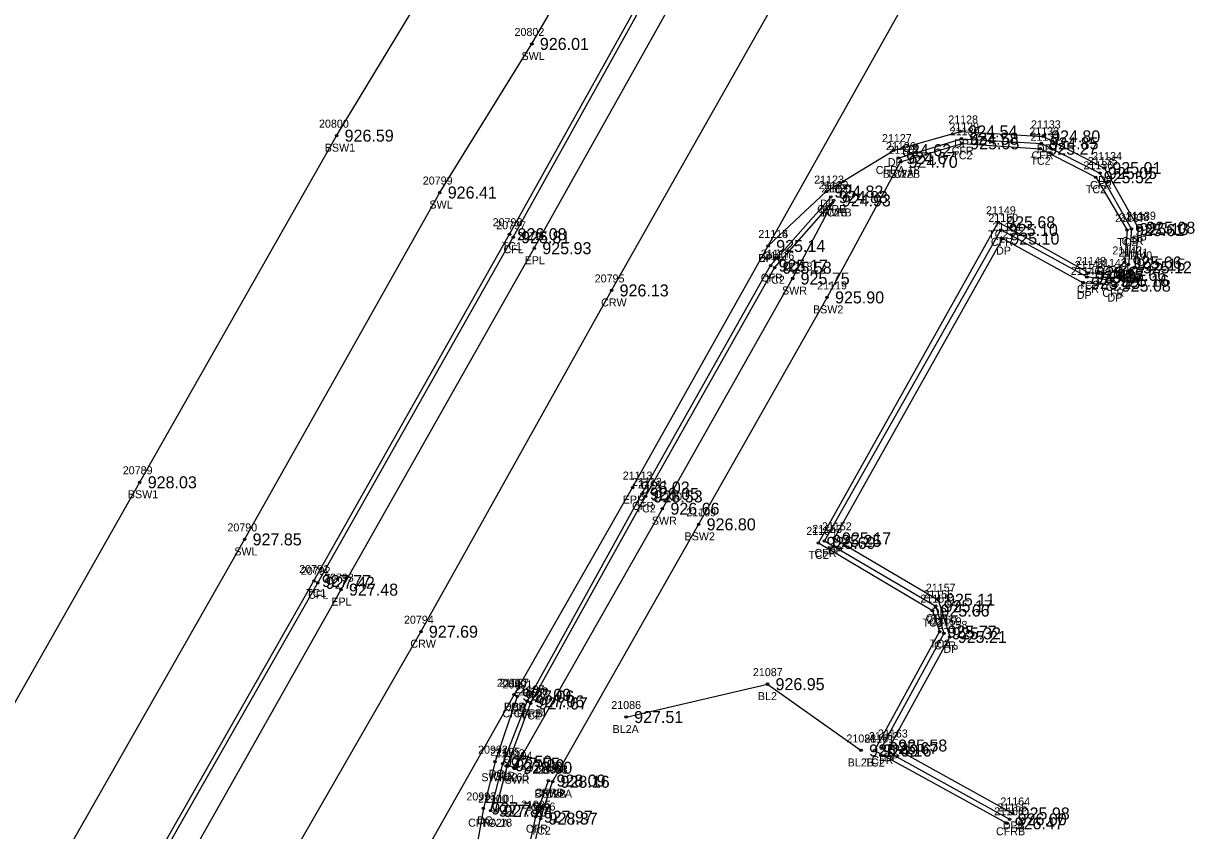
# Model space of a CAD drawing. Extents: x 1576181 to 1577685, y 1099396 to 1101490.
# Drawn here: x 1576724.5 to 1576872.4, y 1100179 to 1100279.9 of the extents above; entities that cross this region are included whole.
import ezdxf

# ---------------------------------------------------------------- set-up
doc = ezdxf.new("R2010")
doc.units = 0
for name, color, linetype in [('RD_DTM_BkLn1', 7, 'Continuous'), ('RD_DTM_BkLn2', 7, 'Continuous'), ('RD_DTM_BkLn_txCode', 7, 'Continuous'), ('RD_EX_Conc', 7, 'Continuous'), ('RD_EX_Conc_txCode', 7, 'Continuous'), ('RD_EX_Driveway', 7, 'Continuous'), ('RD_EX_Driveway_txCode', 7, 'Continuous'), ('RD_EX_Road', 7, 'Continuous'), ('RD_EX_Road_txCode', 7, 'Continuous'), ('RD_EX_TX_Conc_ELEV', 7, 'Continuous'), ('RD_EX_TX_Driveway_ELEV', 7, 'Continuous'), ('RD_EX_TX_Misc_ELEV', 7, 'Continuous'), ('RD_EX_TX_Road_ELEV', 7, 'Continuous'), ('RD_HC_Survey_ELEV', 7, 'Continuous'), ('RD_HC_Survey_txCode', 7, 'Continuous'), ('RD_SMD_Locator', 7, 'Continuous')]:
    doc.layers.add(name, color=color, linetype=linetype)

msp = doc.modelspace()

# ---------------------------------------------------------------- linework, layer by layer
at = {"layer": 'RD_DTM_BkLn1'}
for points in [[(1576435.96, 1099635.47), (1576469.98, 1099685.91), (1576496.51, 1099728.46), (1576522.67, 1099770.85), (1576549.06, 1099813.4), (1576563.36, 1099837.2), (1576575.09, 1099855.95), (1576600.75, 1099898.96), (1576625.57, 1099942.14), (1576652.37, 1099988.91), (1576675.03, 1100029.12), (1576699.51, 1100072.44), (1576723.52, 1100115.7), (1576748.08, 1100158.53), (1576774.13, 1100203.85), (1576797.97, 1100246.52), (1576822.46, 1100289.82), (1576846.93, 1100333.35), (1576871.37, 1100376.46), (1576888.27, 1100406.22)], [(1576799.79, 1100193.18), (1576817.46, 1100197.29), (1576829.16, 1100189)]]:
    msp.add_lwpolyline(points, dxfattribs=at)
at = {"layer": 'RD_DTM_BkLn2'}
for points in [[(1576569.71, 1099889.13), (1576574.56, 1099891.34), (1576579.27, 1099894.47), (1576584.19, 1099899.55), (1576592.25, 1099913.59), (1576612.84, 1099949.87), (1576637.54, 1099993.05), (1576637.54, 1099993.05), (1576662.19, 1100036.34), (1576686.67, 1100079.69), (1576711.46, 1100123.12), (1576735.92, 1100166.59), (1576760.76, 1100210.19), (1576785.21, 1100253.55), (1576809.13, 1100296.43), (1576833.85, 1100340.61), (1576852.06, 1100373.52), (1576858.66, 1100385.37)], [(1576834.09, 1100262.6), (1576841.79, 1100264.91), (1576851.56, 1100264.23), (1576858.48, 1100260.67), (1576862.4, 1100254.06), (1576862.08, 1100250.02), (1576860.15, 1100248.47), (1576857.56, 1100248.71), (1576846.29, 1100255.04), (1576823.82, 1100214.95), (1576838.08, 1100206.49), (1576838.96, 1100203.86), (1576830.82, 1100188.99), (1576847.35, 1100179.89)], [(1576783.46, 1100181.45), (1576784.94, 1100187.15), (1576787.85, 1100194.88), (1576802.21, 1100220.76), (1576818.34, 1100249.36), (1576825.74, 1100257.77)], [(1576787.7, 1100170.21), (1576787.99, 1100175.73), (1576789.09, 1100180.48), (1576790.59, 1100185.09)]]:
    msp.add_lwpolyline(points, dxfattribs=at)
at = {"layer": 'RD_EX_Conc'}
for points in [[(1576537.53, 1099904.47), (1576543.86, 1099909.52), (1576562.16, 1099910.99), (1576591.51, 1099962.44), (1576615.66, 1100005.02), (1576615.66, 1100005.02), (1576639.95, 1100047.65), (1576665.61, 1100092.87), (1576689.57, 1100135.17), (1576714.68, 1100179.66), (1576738.99, 1100222.53), (1576763.6, 1100265.87), (1576774.84, 1100284.48), (1576788.69, 1100308.17), (1576806.14, 1100353.34), (1576815.02, 1100384.28), (1576820.35, 1100399.92), (1576825.22, 1100406.93), (1576832.15, 1100418.17), (1576835.04, 1100423.11), (1576847.13, 1100416.35), (1576868.44, 1100408.23), (1576872.09, 1100412.69)], [(1576592.25, 1099913.59), (1576580.2, 1099912.49), (1576604.17, 1099954.86), (1576628.85, 1099997.89), (1576628.85, 1099997.89), (1576652.81, 1100040.47), (1576678.28, 1100085.17), (1576702.19, 1100127.32), (1576727.43, 1100172.04), (1576752.1, 1100215.39), (1576776.49, 1100258.76), (1576788, 1100277.34), (1576801.96, 1100301.42), (1576820.18, 1100348.3), (1576829.19, 1100379.59), (1576833.87, 1100393.41), (1576838.32, 1100402.43), (1576861.82, 1100391.11)], [(1576569.87, 1099888.69), (1576574.84, 1099890.86), (1576574.84, 1099890.86), (1576579.65, 1099894.15), (1576584.72, 1099899.29), (1576592.68, 1099913.3), (1576613.45, 1099949.72), (1576638.02, 1099992.78), (1576638.02, 1099992.78), (1576662.6, 1100036.05), (1576687.14, 1100079.44), (1576711.91, 1100122.93), (1576736.42, 1100166.35), (1576761.24, 1100209.96), (1576785.67, 1100253.17), (1576809.57, 1100296.25), (1576834.31, 1100340.56), (1576852.46, 1100373.22), (1576852.46, 1100373.22), (1576859.24, 1100385.1)], [(1576833.8, 1100263.07), (1576841.69, 1100265.49), (1576851.69, 1100264.91), (1576859, 1100261.2), (1576862.95, 1100254.19), (1576862.57, 1100249.76), (1576860.52, 1100247.72), (1576857.37, 1100248.21), (1576846.61, 1100254.09), (1576824.56, 1100215.2), (1576838.48, 1100207.04), (1576839.5, 1100203.64), (1576831.67, 1100189.29), (1576847.72, 1100180.39)], [(1576790.59, 1100185.09), (1576808.85, 1100217.27), (1576824.9, 1100245.65), (1576834.09, 1100262.6)], [(1576782.86, 1100181.47), (1576784.37, 1100187.33), (1576787.42, 1100195.14), (1576787.42, 1100195.14), (1576801.76, 1100221.08), (1576817.85, 1100249.62), (1576825.37, 1100258.19)], [(1576784.94, 1100187.15), (1576785.91, 1100186.84), (1576804.32, 1100219.23), (1576820.59, 1100248.01), (1576825.74, 1100257.77)], [(1576785.78, 1100195.96), (1576786.17, 1100195.75), (1576783.4, 1100187.6), (1576781.94, 1100181.75), (1576781.06, 1100176.61), (1576780.68, 1100170.53), (1576780.65, 1100154.57), (1576781.71, 1100148.92), (1576783.02, 1100145.98), (1576783.87, 1100143), (1576785.93, 1100140.68), (1576788.65, 1100139.28), (1576796.67, 1100133.29), (1576804.55, 1100128.57), (1576819.43, 1100122.6)], [(1576787.28, 1100170.17), (1576787.42, 1100175.79), (1576788.49, 1100180.72), (1576790.08, 1100185.23)]]:
    msp.add_lwpolyline(points, dxfattribs=at)
at = {"layer": 'RD_EX_Driveway'}
msp.add_lwpolyline([(1576817.54, 1100252.08), (1576824.8, 1100258.88), (1576833.27, 1100264.06), (1576841.56, 1100266.4), (1576851.91, 1100265.78), (1576859.56, 1100261.82), (1576863.79, 1100254.36), (1576863.37, 1100249.4), (1576860.73, 1100247.12), (1576856.89, 1100247.45), (1576846.81, 1100253), (1576825.77, 1100215.52), (1576838.77, 1100207.85), (1576840.24, 1100203.2), (1576832.79, 1100189.62), (1576848.1, 1100181.12)], dxfattribs=at)
at = {"layer": 'RD_EX_Road'}
for points in [[(1576574.84, 1099890.86), (1576581.17, 1099887.16), (1576595.39, 1099911.97), (1576615.87, 1099948.17), (1576640.56, 1099991.4), (1576640.56, 1099991.4), (1576664.88, 1100034.19), (1576689.84, 1100078.06), (1576714.22, 1100121.19), (1576739.08, 1100164.66), (1576764.15, 1100209.11), (1576788.31, 1100251.8), (1576812.15, 1100294.46), (1576837.06, 1100339.37), (1576855.38, 1100371.53), (1576853.98, 1100372.48), (1576862.98, 1100388.86), (1576865.16, 1100391.95), (1576873.15, 1100402.8), (1576877.45, 1100410.32)], [(1576663.31, 1099979.53), (1576687.43, 1100021.53), (1576712.03, 1100065.1), (1576738.42, 1100112.14), (1576760.61, 1100151.41), (1576785.78, 1100195.96), (1576800.59, 1100221.87), (1576817.54, 1100252.08), (1576858.25, 1100324.63), (1576880.45, 1100364.01), (1576883.5, 1100369.45), (1576896.98, 1100397.71)]]:
    msp.add_lwpolyline(points, dxfattribs=at)
at = {"layer": 'RD_SMD_Locator'}
for centre in [(1576788, 1100277.34), (1576763.6, 1100265.87), (1576841.56, 1100266.4), (1576841.69, 1100265.49), (1576851.91, 1100265.78), (1576833.27, 1100264.06), (1576841.79, 1100264.91), (1576851.56, 1100264.23), (1576851.69, 1100264.91), (1576833.8, 1100263.07), (1576834.09, 1100262.6), (1576834.09, 1100262.6), (1576858.48, 1100260.67), (1576859, 1100261.2), (1576859.56, 1100261.82), (1576776.49, 1100258.76), (1576824.8, 1100258.88), (1576825.37, 1100258.19), (1576825.74, 1100257.77), (1576825.74, 1100257.77), (1576846.29, 1100255.04), (1576785.21, 1100253.55), (1576785.67, 1100253.17), (1576846.61, 1100254.09), (1576862.4, 1100254.06), (1576862.95, 1100254.19), (1576863.79, 1100254.36), (1576788.31, 1100251.8), (1576817.54, 1100252.08), (1576817.54, 1100252.08), (1576846.81, 1100253), (1576817.85, 1100249.62), (1576818.34, 1100249.36), (1576857.56, 1100248.71), (1576862.08, 1100250.02), (1576862.57, 1100249.76), (1576863.37, 1100249.4), (1576820.59, 1100248.01), (1576856.89, 1100247.45), (1576857.37, 1100248.21), (1576860.15, 1100248.47), (1576860.52, 1100247.72), (1576797.97, 1100246.52), (1576860.73, 1100247.12), (1576824.9, 1100245.65), (1576738.99, 1100222.53), (1576800.59, 1100221.87), (1576801.76, 1100221.08), (1576802.21, 1100220.76), (1576804.32, 1100219.23), (1576808.85, 1100217.27), (1576752.1, 1100215.39), (1576823.82, 1100214.95), (1576824.56, 1100215.2), (1576825.77, 1100215.52), (1576760.76, 1100210.19), (1576761.24, 1100209.96), (1576764.15, 1100209.11), (1576838.77, 1100207.85), (1576838.08, 1100206.49), (1576838.48, 1100207.04), (1576774.13, 1100203.85), (1576838.96, 1100203.86), (1576839.5, 1100203.64), (1576840.24, 1100203.2), (1576817.46, 1100197.29), (1576785.78, 1100195.96), (1576785.78, 1100195.96), (1576786.17, 1100195.75), (1576787.42, 1100195.14), (1576787.42, 1100195.14), (1576787.85, 1100194.88), (1576799.79, 1100193.18), (1576832.79, 1100189.62), (1576829.16, 1100189), (1576830.82, 1100188.99), (1576831.67, 1100189.29), (1576783.4, 1100187.6), (1576784.37, 1100187.33), (1576784.94, 1100187.15), (1576784.94, 1100187.15), (1576785.91, 1100186.84), (1576790.08, 1100185.23), (1576790.59, 1100185.09), (1576790.59, 1100185.09), (1576781.94, 1100181.75), (1576782.86, 1100181.47), (1576783.46, 1100181.45), (1576788.49, 1100180.72), (1576848.1, 1100181.12), (1576789.09, 1100180.48), (1576847.35, 1100179.89), (1576847.72, 1100180.39)]:
    msp.add_circle(centre, 0.15, dxfattribs=at)

# ---------------------------------------------------------------- texts
at = {"layer": 'RD_DTM_BkLn_txCode'}
for s, p in [('21087', (1576815.63, 1100198.29)), ('BL2', (1576816.26, 1100195.29)), ('21086', (1576797.93, 1100194.18)), ('BL2A', (1576798.09, 1100191.18)), ('21088', (1576827.32, 1100190)), ('BL2B', (1576827.48, 1100187))]:
    msp.add_text(s, height=1, dxfattribs=at).set_placement(p)
at = {"layer": 'RD_EX_Conc_txCode'}
for s, p in [('20802', (1576785.84, 1100278.34)), ('SWL', (1576786.71, 1100275.34)), ('20800', (1576761.4, 1100266.87)), ('21129', (1576840.18, 1100266.49)), ('21130', (1576840.24, 1100265.91)), ('21132', (1576850.18, 1100265.91)), ('21131', (1576850.33, 1100265.23)), ('BSW1', (1576762.12, 1100263.87)), ('21126', (1576832.26, 1100264.07)), ('21124', (1576832.57, 1100263.6)), ('21125', (1576832.57, 1100263.6)), ('CFR', (1576840.47, 1100263.49)), ('TC2', (1576840.55, 1100262.91)), ('CFR', (1576850.46, 1100262.91)), ('TC2', (1576850.32, 1100262.23)), ('21136', (1576856.95, 1100261.67)), ('21135', (1576857.49, 1100262.2)), ('20799', (1576774.37, 1100259.76)), ('CFRA 18', (1576830.98, 1100261.07)), ('BSW2B', (1576831.85, 1100260.6)), ('TC2A', (1576832.35, 1100260.6)), ('21122', (1576823.86, 1100259.19)), ('21120', (1576824.19, 1100258.77)), ('21121', (1576824.51, 1100258.77)), ('TC2', (1576857.24, 1100258.67)), ('CFR', (1576857.77, 1100259.2)), ('SWL', (1576775.2, 1100256.76)), ('CFRB', (1576823.67, 1100256.19)), ('SWRB', (1576823.96, 1100255.77)), ('TC2B', (1576824.03, 1100255.77)), ('21149', (1576844.77, 1100256.04)), ('20798', (1576783.1, 1100254.55)), ('20797', (1576783.55, 1100254.17)), ('21150', (1576845.06, 1100255.09)), ('21137', (1576860.89, 1100255.06)), ('21138', (1576861.44, 1100255.19)), ('TC2', (1576845.04, 1100253.04)), ('TC1', (1576784.25, 1100251.55)), ('CFL', (1576784.46, 1100251.17)), ('CFR', (1576845.38, 1100252.09)), ('21142', (1576860.56, 1100251.02)), ('TC2', (1576861.16, 1100252.06)), ('CFR', (1576861.72, 1100252.19)), ('21117', (1576816.62, 1100250.62)), ('21116', (1576817.08, 1100250.36)), ('21148', (1576856.05, 1100249.71)), ('21143', (1576858.64, 1100249.47)), ('21141', (1576861.34, 1100250.76)), ('21118', (1576819.36, 1100249.01)), ('21147', (1576855.86, 1100249.21)), ('21144', (1576859.01, 1100248.72)), ('TC2', (1576860.83, 1100248.02)), ('CFR', (1576816.62, 1100247.62)), ('TC2', (1576817.09, 1100247.36)), ('21119', (1576823.67, 1100246.65)), ('TC2', (1576856.32, 1100246.71)), ('TC2', (1576858.9, 1100246.47)), ('CFR', (1576861.34, 1100247.76)), ('SWR', (1576819.27, 1100246.01)), ('CFR', (1576856.14, 1100246.21)), ('CFR', (1576859.3, 1100245.72)), ('BSW2', (1576823.14, 1100243.65)), ('20789', (1576736.87, 1100223.53)), ('21112', (1576800.53, 1100222.08)), ('21111', (1576801.26, 1100221.76)), ('BSW1', (1576737.51, 1100220.53)), ('21110', (1576803.05, 1100220.23)), ('CFR', (1576800.53, 1100219.08)), ('TC2', (1576800.96, 1100218.76)), ('21109', (1576807.3, 1100218.27)), ('SWR', (1576803, 1100217.23)), ('20790', (1576749.95, 1100216.39)), ('BSW2', (1576807.09, 1100215.27)), ('21154', (1576822.31, 1100215.95)), ('21153', (1576823.05, 1100216.2)), ('SWL', (1576750.81, 1100213.39)), ('TC2', (1576822.58, 1100212.95)), ('CFR', (1576823.33, 1100213.2)), ('20791', (1576758.92, 1100211.19)), ('20792', (1576759.12, 1100210.96)), ('TC1', (1576759.79, 1100208.19)), ('CFL', (1576760.04, 1100207.96)), ('21156', (1576836.95, 1100208.04)), ('21155', (1576836.57, 1100207.49)), ('CFR', (1576837.25, 1100205.04)), ('TC2', (1576836.83, 1100204.49)), ('21160', (1576837.39, 1100204.86)), ('21159', (1576837.99, 1100204.64)), ('TC2', (1576837.72, 1100201.86)), ('CFR', (1576838.27, 1100201.64)), ('20990', (1576783.62, 1100196.96)), ('20991', (1576784.34, 1100196.75)), ('21106', (1576785.85, 1100196.14)), ('21107', (1576785.87, 1100196.14)), ('21108', (1576786.3, 1100195.88)), ('CFRA 24', (1576784.32, 1100193.14)), ('DCA', (1576784.51, 1100193.96)), ('DC', (1576785.39, 1100193.75)), ('CFRB', (1576785.72, 1100193.14)), ('TC2', (1576786.61, 1100192.88)), ('21162', (1576830.13, 1100190.29)), ('21161', (1576829.57, 1100189.99)), ('20992', (1576781.28, 1100188.6)), ('21105', (1576782.82, 1100188.33)), ('21102', (1576783.39, 1100188.15)), ('21103', (1576783.39, 1100188.15)), ('21104', (1576784.36, 1100187.84)), ('CFR', (1576830.44, 1100187.29)), ('21099', (1576788.24, 1100186.23)), ('21097', (1576788.76, 1100186.09)), ('21098', (1576788.76, 1100186.09)), ('TC2', (1576829.58, 1100186.99)), ('SWRA 60', (1576781.69, 1100185.15)), ('DC', (1576782.62, 1100185.6)), ('CFR', (1576783.15, 1100185.33)), ('TC2', (1576783.69, 1100185.15)), ('SWR', (1576784.6, 1100184.84)), ('20993', (1576779.82, 1100182.75)), ('CFRB', (1576788.37, 1100183.23)), ('BSW2A', (1576788.34, 1100183.09)), ('TC2B', (1576788.88, 1100183.09)), ('21100', (1576781.27, 1100182.47)), ('21101', (1576782.19, 1100182.45)), ('21095', (1576786.65, 1100181.72)), ('21096', (1576787.23, 1100181.48)), ('21165', (1576846.19, 1100181.39)), ('21166', (1576845.79, 1100180.89)), ('CFRA 18', (1576780.04, 1100179.47)), ('DC', (1576781.16, 1100179.75)), ('TC2A', (1576781.73, 1100179.45)), ('CFR', (1576787.26, 1100178.72)), ('TC2', (1576787.84, 1100178.48)), ('CFRB', (1576846.02, 1100178.39))]:
    msp.add_text(s, height=1, dxfattribs=at).set_placement(p)
at = {"layer": 'RD_EX_Driveway_txCode'}
for s, p in [('21128', (1576840.05, 1100267.4)), ('21133', (1576850.39, 1100266.78)), ('21127', (1576831.76, 1100265.06)), ('DP', (1576840.78, 1100264.4)), ('DP', (1576851.13, 1100263.78)), ('21134', (1576858.04, 1100262.82)), ('DP', (1576832.49, 1100262.06)), ('21123', (1576823.29, 1100259.88)), ('DP', (1576858.78, 1100259.82)), ('DP', (1576824.02, 1100256.88)), ('21139', (1576862.28, 1100255.36)), ('21151', (1576845.58, 1100254)), ('21115', (1576816.31, 1100253.08)), ('DP', (1576863.01, 1100252.36)), ('DP', (1576846.03, 1100251)), ('DPA', (1576816.28, 1100250.08)), ('21140', (1576861.82, 1100250.4)), ('21146', (1576855.36, 1100248.45)), ('21145', (1576859.21, 1100248.12)), ('DP', (1576862.59, 1100247.4)), ('DP', (1576856.11, 1100245.45)), ('DP', (1576859.95, 1100245.12)), ('21152', (1576824.26, 1100216.52)), ('DP', (1576824.99, 1100213.52)), ('21157', (1576837.25, 1100208.85)), ('DP', (1576837.99, 1100205.85)), ('21158', (1576838.72, 1100204.2)), ('DP', (1576839.46, 1100201.2)), ('21163', (1576831.26, 1100190.62)), ('DP', (1576832.01, 1100187.62)), ('21164', (1576846.56, 1100182.12)), ('DPB', (1576846.85, 1100179.12))]:
    msp.add_text(s, height=1, dxfattribs=at).set_placement(p)
at = {"layer": 'RD_EX_Road_txCode'}
for s, p in [('20796', (1576786.17, 1100252.8)), ('21114', (1576816.31, 1100253.08)), ('EPL', (1576787.1, 1100249.8)), ('EPR', (1576816.31, 1100250.08)), ('21113', (1576799.36, 1100222.87)), ('EPR', (1576799.36, 1100219.87)), ('20793', (1576762.03, 1100210.11)), ('EPL', (1576762.94, 1100207.11)), ('21067', (1576783.92, 1100196.96)), ('EPR', (1576784.55, 1100193.96))]:
    msp.add_text(s, height=1, dxfattribs=at).set_placement(p)
at = {"layer": 'RD_EX_TX_Conc_ELEV'}
for s, p in [('926.01', (1576789, 1100276.59)), ('926.59', (1576764.6, 1100265.12)), ('924.58', (1576842.69, 1100264.74)), ('925.05', (1576842.79, 1100264.16)), ('924.85', (1576852.69, 1100264.16)), ('924.67', (1576834.8, 1100262.32)), ('925.27', (1576852.56, 1100263.48)), ('924.70', (1576835.09, 1100261.85)), ('924.70', (1576835.09, 1100261.85)), ('925.52', (1576859.48, 1100259.92)), ('925.05', (1576860, 1100260.45)), ('926.41', (1576777.49, 1100258.01)), ('924.83', (1576826.37, 1100257.44)), ('924.93', (1576826.74, 1100257.02)), ('924.93', (1576826.74, 1100257.02)), ('925.68', (1576847.29, 1100254.29)), ('925.10', (1576847.61, 1100253.34)), ('925.61', (1576863.4, 1100253.31)), ('925.13', (1576863.95, 1100253.44)), ('926.08', (1576786.21, 1100252.8)), ('925.81', (1576786.67, 1100252.42)), ('925.17', (1576818.85, 1100248.87)), ('925.66', (1576863.08, 1100249.27)), ('925.15', (1576863.57, 1100249.01)), ('925.58', (1576819.34, 1100248.61)), ('925.17', (1576858.37, 1100247.46)), ('925.67', (1576858.56, 1100247.96)), ('925.66', (1576861.15, 1100247.72)), ('925.75', (1576821.59, 1100247.26)), ('925.16', (1576861.52, 1100246.97)), ('925.90', (1576825.9, 1100244.9)), ('928.03', (1576739.99, 1100221.78)), ('926.05', (1576802.76, 1100220.33)), ('926.53', (1576803.21, 1100220.01)), ('926.66', (1576805.32, 1100218.48)), ('926.80', (1576809.85, 1100216.52)), ('927.85', (1576753.1, 1100214.64)), ('925.69', (1576824.82, 1100214.2)), ('925.25', (1576825.56, 1100214.45)), ('927.77', (1576761.76, 1100209.44)), ('927.42', (1576762.24, 1100209.21)), ('925.17', (1576839.48, 1100206.29)), ('925.66', (1576839.08, 1100205.74)), ('925.77', (1576839.96, 1100203.11)), ('925.32', (1576840.5, 1100202.89)), ('927.09', (1576786.78, 1100195.21)), ('927.06', (1576787.17, 1100195)), ('927.06', (1576788.42, 1100194.39)), ('927.06', (1576788.42, 1100194.39)), ('927.67', (1576788.85, 1100194.13)), ('926.16', (1576831.82, 1100188.24)), ('925.67', (1576832.67, 1100188.54)), ('927.50', (1576784.4, 1100186.85)), ('927.55', (1576785.37, 1100186.58)), ('927.99', (1576785.94, 1100186.4)), ('927.99', (1576785.94, 1100186.4)), ('928.00', (1576786.91, 1100186.09)), ('928.09', (1576791.08, 1100184.48)), ('928.16', (1576791.59, 1100184.34)), ('928.16', (1576791.59, 1100184.34)), ('927.73', (1576782.94, 1100181)), ('927.80', (1576783.86, 1100180.72)), ('927.84', (1576784.46, 1100180.7)), ('927.97', (1576789.49, 1100179.97)), ('928.37', (1576790.09, 1100179.73)), ('926.00', (1576848.72, 1100179.64)), ('926.47', (1576848.35, 1100179.14))]:
    msp.add_text(s, height=1.5, dxfattribs=at).set_placement(p)
at = {"layer": 'RD_EX_TX_Driveway_ELEV'}
for s, p in [('924.54', (1576842.56, 1100265.65)), ('924.80', (1576852.91, 1100265.03)), ('924.62', (1576834.27, 1100263.31)), ('925.01', (1576860.56, 1100261.07)), ('924.82', (1576825.8, 1100258.13)), ('925.08', (1576864.79, 1100253.61)), ('925.10', (1576847.81, 1100252.25)), ('925.14', (1576818.54, 1100251.33)), ('925.12', (1576864.37, 1100248.65)), ('925.15', (1576857.89, 1100246.7)), ('925.08', (1576861.73, 1100246.37)), ('925.17', (1576826.77, 1100214.77)), ('925.11', (1576839.77, 1100207.1)), ('925.21', (1576841.24, 1100202.45)), ('925.58', (1576833.79, 1100188.87)), ('925.98', (1576849.1, 1100180.37))]:
    msp.add_text(s, height=1.5, dxfattribs=at).set_placement(p)
at = {"layer": 'RD_EX_TX_Misc_ELEV'}
for s, p in [('926.95', (1576818.46, 1100196.54)), ('927.51', (1576800.79, 1100192.43)), ('926.49', (1576830.16, 1100188.25))]:
    msp.add_text(s, height=1.5, dxfattribs=at).set_placement(p)
at = {"layer": 'RD_EX_TX_Road_ELEV'}
for s, p in [('925.93', (1576789.31, 1100251.05)), ('925.14', (1576818.54, 1100251.33)), ('926.02', (1576801.59, 1100221.12)), ('927.48', (1576765.15, 1100208.36)), ('927.09', (1576786.78, 1100195.21))]:
    msp.add_text(s, height=1.5, dxfattribs=at).set_placement(p)
at = {"layer": 'RD_HC_Survey_ELEV'}
for s, p in [('926.13', (1576798.97, 1100245.77)), ('927.69', (1576775.13, 1100203.1))]:
    msp.add_text(s, height=1.5, dxfattribs=at).set_placement(p)
at = {"layer": 'RD_HC_Survey_txCode'}
for s, p in [('20795', (1576795.86, 1100247.52)), ('CRW', (1576796.66, 1100244.52)), ('20794', (1576772.02, 1100204.85)), ('CRW', (1576772.82, 1100201.85))]:
    msp.add_text(s, height=1, dxfattribs=at).set_placement(p)

doc.saveas('drawing.dxf')
